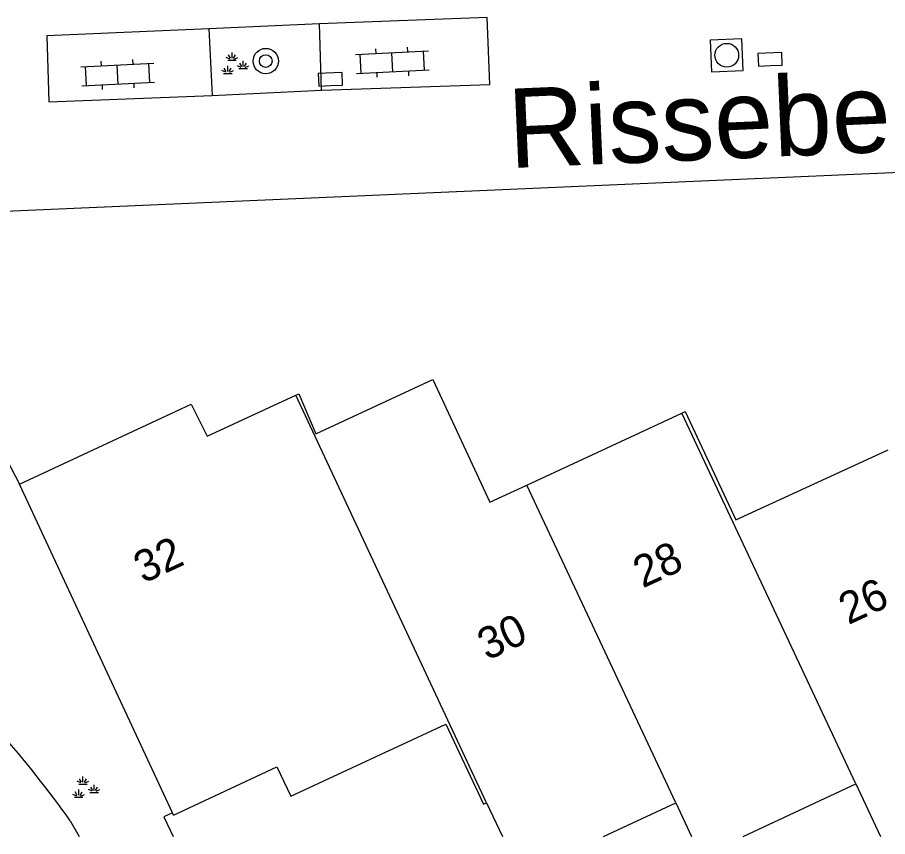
# Model space of a CAD drawing. Extents: x 128999 to 131010, y 395498 to 399007.
# Drawn here: x 130847.25 to 130874.7, y 395500 to 395525.84 of the extents above; entities that cross this region are included whole.
import ezdxf

# ---------------------------------------------------------------- set-up
doc = ezdxf.new("R2010")
doc.units = 0
for name, color, linetype in [('gg-afsc-muur', 7, 'Continuous'), ('gg-anno-huisnummerreeks BGT', 7, 'Continuous'), ('gg-anno-openbare ruimte label', 7, 'Continuous'), ('gg-bbg-gedigitaliseerde bebouwing', 7, 'Continuous'), ('gg-bbg-hoofdgebouw', 7, 'Continuous'), ('gg-bbg-tussenscheiding', 7, 'Continuous'), ('gg-knt-onverhard', 7, 'Continuous'), ('gg-knt-verharding', 7, 'Continuous'), ('gg-knt-verharding nz', 7, 'Continuous'), ('gt-grn-groengrens', 7, 'Continuous'), ('gt-symb-boom', 7, 'Continuous'), ('gt-symb-groenvak', 7, 'Continuous'), ('gt-symb-klinker verharding', 7, 'Continuous'), ('gt-symb-kolk', 7, 'Continuous'), ('gt-symb-rioolschacht', 7, 'Continuous')]:
    doc.layers.add(name, color=color, linetype=linetype)

# ---------------------------------------------------------------- blocks, each defined once
blk = doc.blocks.new('gt0-KL1')
at = {"layer": 'gt-symb-klinker verharding'}
for p, q in [((-1.15, 0.3), (1.15, 0.3)), ((-1, -0.3), (-1, 0.3)), ((-0.5, 0.3), (-0.5, 0.45)), ((0, -0.3), (0, 0.3)), ((0.5, 0.3), (0.5, 0.45)), ((1, -0.3), (1, 0.3)), ((-1.15, -0.3), (1.15, -0.3)), ((-0.5, -0.45), (-0.5, -0.3)), ((0.5, -0.45), (0.5, -0.3))]:
    blk.add_line(p, q, dxfattribs=at)
blk = doc.blocks.new('gt0-GRVAK')
at = {"layer": 'gt-symb-groenvak'}
for p, q in [((-0.091, 0.211), (-0.156, 0.322)), ((-0.047, 0.214), (-0.047, 0.393)), ((-0.004, 0.211), (0.061, 0.322)), ((-0.11, 0.189), (-0.228, 0.24)), ((-0.182, 0.153), (0.088, 0.153)), ((0.015, 0.189), (0.133, 0.24)), ((0.262, -0.052), (0.197, 0.059)), ((0.305, -0.049), (0.305, 0.13)), ((0.349, -0.052), (0.414, 0.059)), ((-0.245, -0.228), (-0.363, -0.177)), ((-0.318, -0.264), (-0.047, -0.264)), ((-0.226, -0.206), (-0.291, -0.095)), ((-0.183, -0.203), (-0.183, -0.024)), ((-0.139, -0.206), (-0.074, -0.095)), ((-0.12, -0.228), (-0.002, -0.177)), ((0.243, -0.074), (0.125, -0.023)), ((0.17, -0.11), (0.441, -0.11)), ((0.368, -0.074), (0.486, -0.023))]:
    blk.add_line(p, q, dxfattribs=at)
blk = doc.blocks.new('gt0-BOOM')
at = {"layer": 'gt-symb-boom'}
for radius in [0.4, 0.2]:
    blk.add_circle((0, 0), radius, dxfattribs=at)
blk = doc.blocks.new('gt0-RS')
at = {"layer": 'gt-symb-rioolschacht'}
blk.add_lwpolyline([(-0.5, -0.5), (0.5, -0.5), (0.5, 0.5), (-0.5, 0.5)], close=True, dxfattribs=at)
blk.add_circle((0, 0), 0.375, dxfattribs=at)
blk = doc.blocks.new('gt0-KOLK')
at = {"layer": 'gt-symb-kolk'}
blk.add_lwpolyline([(0, 0), (0.375, 0), (0.375, 0.4), (-0.375, 0.4), (-0.375, 0), (0, 0)], dxfattribs=at)

msp = doc.modelspace()

# ---------------------------------------------------------------- linework, layer by layer
at = {"layer": 'gg-afsc-muur'}
msp.add_lwpolyline([(130852.135, 395500.748), (130851.865, 395500.623), (130852.156, 395500)], dxfattribs=at)
at = {"layer": 'gg-bbg-gedigitaliseerde bebouwing'}
for p, q in [((130870.143, 395500), (130873.701, 395501.66)), ((130873.701, 395501.66), (130874.476, 395500)), ((130862.05, 395501.07), (130862.549, 395500)), ((130865.743, 395500), (130868.018, 395501.062)), ((130868.018, 395501.062), (130868.514, 395500))]:
    msp.add_line(p, q, dxfattribs=at)
msp.add_lwpolyline([(130852.167, 395500.68), (130855.436, 395502.203), (130855.87, 395501.27), (130860.76, 395503.55), (130861.95, 395501.02), (130862.05, 395501.07)], dxfattribs=at)
at = {"layer": 'gg-bbg-hoofdgebouw'}
for p, q in [((130863.325, 395511.088), (130868.212, 395513.358)), ((130852.135, 395500.748), (130847.31, 395511.112)), ((130852.167, 395500.68), (130852.135, 395500.748))]:
    msp.add_line(p, q, dxfattribs=at)
for points in [[(130856.036, 395513.924), (130856.123, 395513.964), (130856.667, 395512.7), (130860.354, 395514.423), (130862.155, 395510.545), (130863.325, 395511.088)], [(130847.31, 395511.112), (130852.731, 395513.641), (130853.236, 395512.631), (130856.036, 395513.924)], [(130868.212, 395513.358), (130868.317, 395513.407), (130869.917, 395509.99), (130874.719, 395512.204)]]:
    msp.add_lwpolyline(points, dxfattribs=at)
at = {"layer": 'gg-bbg-tussenscheiding'}
for p, q in [((130862.05, 395501.07), (130856.036, 395513.924)), ((130873.701, 395501.66), (130868.212, 395513.358)), ((130868.018, 395501.062), (130863.325, 395511.088))]:
    msp.add_line(p, q, dxfattribs=at)
at = {"layer": 'gg-knt-onverhard'}
msp.add_line((130848.914, 395500.501), (130849.197, 395500), dxfattribs=at)
msp.add_arc((130818.697, 395478.873), 37.159, 35.593, 46.608, dxfattribs=at)
at = {"layer": 'gg-knt-verharding'}
for p, q in [((130856.775, 395525.634), (130853.291, 395525.477)), ((130853.291, 395525.477), (130853.39, 395523.379)), ((130856.841, 395523.547), (130856.775, 395525.634)), ((130853.39, 395523.379), (130856.841, 395523.547)), ((130842.922, 395519.552), (130879.44, 395521.143))]:
    msp.add_line(p, q, dxfattribs=at)
at = {"layer": 'gg-knt-verharding nz'}
for points in [[(130856.841, 395523.547), (130862.154, 395523.72), (130862.064, 395525.839), (130856.775, 395525.634)], [(130853.291, 395525.477), (130848.169, 395525.256), (130848.235, 395523.177), (130853.39, 395523.379)]]:
    msp.add_lwpolyline(points, dxfattribs=at)
at = {"layer": 'gt-grn-groengrens'}
msp.add_line((130842.922, 395519.552), (130847.31, 395511.112), dxfattribs=at)

# ---------------------------------------------------------------- block references
at = {"layer": 'gt-symb-boom'}
msp.add_blockref('gt0-BOOM', (130855.082, 395524.463), dxfattribs=at)
at = {"layer": 'gt-symb-groenvak'}
for p in [(130854.064, 395524.338), (130849.362, 395501.505)]:
    msp.add_blockref('gt0-GRVAK', p, dxfattribs=at)
at = {"layer": 'gt-symb-klinker verharding'}
for p, rotation in [((130859.078, 395524.426), 2.750834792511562), ((130850.411, 395524.038), 2.7508347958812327)]:
    msp.add_blockref('gt0-KL1', p, dxfattribs=dict(at, rotation=rotation))
at = {"layer": 'gt-symb-kolk'}
for p, rotation in [((130871.004, 395524.317), 2.407413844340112), ((130857.132, 395523.687), 2.407413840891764)]:
    msp.add_blockref('gt0-KOLK', p, dxfattribs=dict(at, rotation=rotation))
at = {"layer": 'gt-symb-rioolschacht', "rotation": -177.64984047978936}
msp.add_blockref('gt0-RS', (130869.629, 395524.645), dxfattribs=at)

# ---------------------------------------------------------------- texts
at = {"layer": 'gg-anno-huisnummerreeks BGT'}
for s, rotation, p in [('32', 25, (130851.221, 395507.971)), ('28', 24.9, (130866.975, 395507.822)), ('26', 24.8, (130873.462, 395506.668)), ('30', 24.9, (130862.065, 395505.542))]:
    msp.add_text(s, height=1, rotation=rotation, dxfattribs=at).set_placement(p)
at = {"layer": 'gg-anno-openbare ruimte label'}
msp.add_text('Rissebeek', height=2.5, rotation=2.5, dxfattribs=at).set_placement((130862.78, 395521.084))

doc.saveas('drawing.dxf')
